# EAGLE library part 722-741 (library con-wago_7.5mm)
Serie 722, Federleiste mit geraden Einlötstiften / Series 722, Female connector with straight solder pins Polzahl / Pole No.: 11 Rastermaß / Pitch: 7.5 mm Bemessungsspannung / Rated Voltage: 630 V Nennstrom / Nominal Current: 12 A Lötstiftlänge: / Solder Pin Length: 5 mm Farbe / Color: lichtgrau / light gray Stand: 01.01.2012. Die jeweils aktuellen Daten zu diesem Artikel finden Sie in unserem Produktkatalog, den Sie unter www.wago.com einsehen können. As of: 01/01/2012. Please find the newest data for this article in our product catalogue, which can be viewed under www.wago.com.
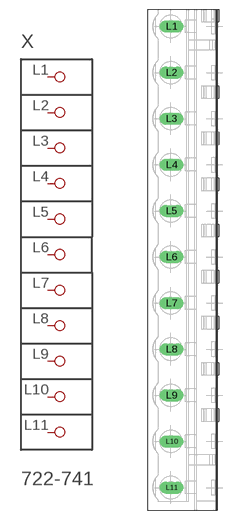
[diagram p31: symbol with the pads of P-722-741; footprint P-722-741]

Designator prefix X

## 722-741  [P-722-741]
L1  P1
L2  P2
L3  P3
L4  P4
L5  P5
L6  P6
L7  P7
L8  P8
L9  P9
L10  P10
L11  P11

## Footprint P-722-741 (pad centres in mm)
drill 1.3 long: L1 -2.166,37.95; L2 -2.166,30.45; L3 -2.166,22.95; L4 -2.166,15.45; L5 -2.166,7.95; L6 -2.166,0.45; L7 -2.166,-7.05; L8 -2.166,-14.55; L9 -2.166,-22.05; L10 -2.166,-29.55; L11 -2.166,-37.05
